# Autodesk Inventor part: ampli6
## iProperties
Created: 2009-06
Part Number: ampli6
Document SubType Name: Modeling
Designer: ajtco
Manufacturer: Standard
Standards Organization: Custom
Author: ajtco
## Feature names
1. Extrusion1
2. Extrusion2
3. Extrusion3
